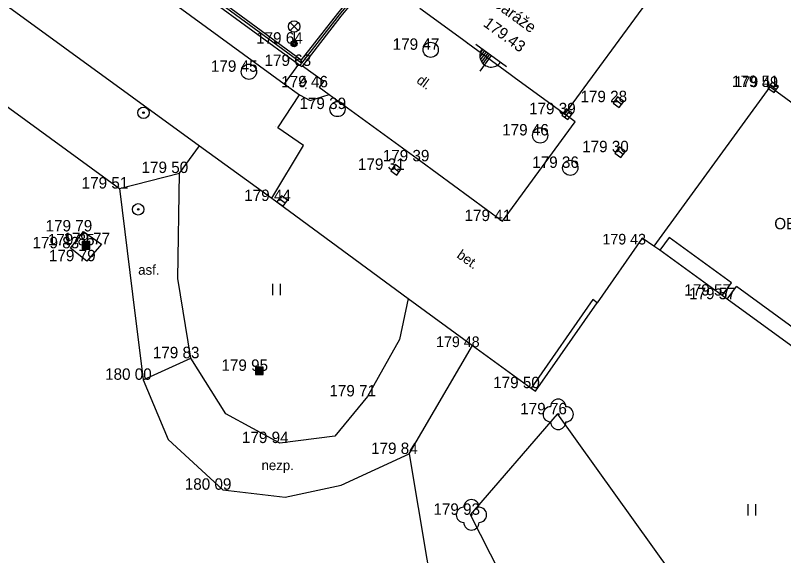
# Model space of a CAD drawing. Extents: x -537755 to -537431, y -1180722 to -1180510.
# Drawn here: x -537528.9 to -537478.3, y -1180686.8 to -1180651.3 of the extents above; entities that cross this region are included whole.
import ezdxf

# ---------------------------------------------------------------- set-up
doc = ezdxf.new("R2010")
doc.units = 0
for name, color, linetype in [('Vrstva 1', 7, 'Continuous'), ('Vrstva 10', 7, 'Continuous'), ('Vrstva 11', 7, 'Continuous'), ('Vrstva 21', 7, 'Continuous'), ('Vrstva 22', 7, 'Continuous'), ('Vrstva 23', 7, 'Continuous'), ('Vrstva 25', 7, 'Continuous'), ('Vrstva 27', 7, 'Continuous'), ('Vrstva 3', 7, 'Continuous'), ('Vrstva 33', 7, 'Continuous'), ('Vrstva 36', 7, 'Continuous'), ('Vrstva 37', 7, 'Continuous'), ('Vrstva 4', 7, 'Continuous'), ('Vrstva 40', 7, 'Continuous'), ('Vrstva 41', 7, 'Continuous'), ('Vrstva 5', 7, 'Continuous'), ('Vrstva 6', 7, 'Continuous'), ('Vrstva 7', 7, 'Continuous')]:
    doc.layers.add(name, color=color, linetype=linetype)

msp = doc.modelspace()

# ---------------------------------------------------------------- linework, layer by layer
at = {"layer": 'Vrstva 1'}
for p, q in [((-537507.45, -1180651.33), (-537507.45, -1180651.33)), ((-537510.53, -1180653.13), (-537510.53, -1180653.13)), ((-537510.5, -1180653.11), (-537510.5, -1180653.11)), ((-537499.14, -1180653.14), (-537499.14, -1180653.14)), ((-537501.548, -1180653.535), (-537501.548, -1180653.535)), ((-537513.5, -1180654.98), (-537513.5, -1180654.98)), ((-537510.02, -1180654.63), (-537510.02, -1180654.63)), ((-537509.99, -1180654.62), (-537509.99, -1180654.62)), ((-537509.973, -1180654.595), (-537509.973, -1180654.595)), ((-537508.78, -1180655.46), (-537508.78, -1180655.46)), ((-537496, -1180655.44), (-537496, -1180655.44)), ((-537511.18, -1180655.77), (-537511.18, -1180655.77)), ((-537508.873, -1180656.001), (-537508.873, -1180656.001)), ((-537508.577, -1180655.601), (-537508.577, -1180655.601)), ((-537479.24, -1180655.98), (-537479.24, -1180655.98)), ((-537479.24, -1180655.99), (-537479.24, -1180655.99)), ((-537510.18, -1180656.5), (-537510.18, -1180656.5)), ((-537509.7, -1180656.54), (-537509.7, -1180656.54)), ((-537489.2, -1180656.98), (-537489.2, -1180656.98)), ((-537507.678, -1180657.432), (-537507.678, -1180657.432)), ((-537507.61, -1180657.4), (-537507.61, -1180657.4)), ((-537492.72, -1180657.76), (-537492.72, -1180657.76)), ((-537492.69, -1180657.74), (-537492.69, -1180657.74)), ((-537492.58, -1180657.77), (-537492.58, -1180657.77)), ((-537492.053, -1180658.278), (-537492.053, -1180658.278)), ((-537511.76, -1180658.6), (-537511.76, -1180658.6)), ((-537494.348, -1180659.167), (-537494.348, -1180659.167)), ((-537494.32, -1180659.15), (-537494.32, -1180659.15)), ((-537516.93, -1180659.72), (-537516.93, -1180659.72)), ((-537509.92, -1180659.83), (-537509.92, -1180659.83)), ((-537489.09, -1180660.27), (-537489.09, -1180660.27)), ((-537489.08, -1180660.25), (-537489.08, -1180660.25)), ((-537502.201, -1180660.87), (-537502.201, -1180660.87)), ((-537503.83, -1180661.43), (-537503.83, -1180661.43)), ((-537503.77, -1180661.45), (-537503.77, -1180661.45)), ((-537492.37, -1180661.3), (-537492.37, -1180661.3)), ((-537492.33, -1180661.28), (-537492.33, -1180661.28)), ((-537518.17, -1180661.68), (-537518.17, -1180661.68)), ((-537518.06, -1180661.64), (-537518.06, -1180661.64)), ((-537522.01, -1180662.53), (-537522.01, -1180662.53)), ((-537522, -1180662.66), (-537522, -1180662.66)), ((-537511.99, -1180663.3), (-537511.99, -1180663.3)), ((-537511.31, -1180663.48), (-537511.31, -1180663.48)), ((-537511.28, -1180663.47), (-537511.28, -1180663.47)), ((-537520.78, -1180664.03), (-537520.78, -1180664.03)), ((-537496.821, -1180664.799), (-537496.821, -1180664.799)), ((-537524.37, -1180665.48), (-537524.37, -1180665.48)), ((-537487.61, -1180665.88), (-537487.61, -1180665.88)), ((-537525.23, -1180666.59), (-537525.23, -1180666.59)), ((-537524.24, -1180666.41), (-537524.24, -1180666.41)), ((-537524.22, -1180666.39), (-537524.22, -1180666.39)), ((-537524.22, -1180666.45), (-537524.22, -1180666.45)), ((-537523.2, -1180666.32), (-537523.2, -1180666.32)), ((-537487.92, -1180666.34), (-537487.92, -1180666.34)), ((-537486.87, -1180666.46), (-537486.87, -1180666.46)), ((-537486.86, -1180666.44), (-537486.86, -1180666.44)), ((-537486.47, -1180666.72), (-537486.47, -1180666.72)), ((-537524.15, -1180667.44), (-537524.15, -1180667.44)), ((-537518.17, -1180668.57), (-537518.17, -1180668.57)), ((-537518.14, -1180669.12), (-537518.14, -1180669.12)), ((-537521.16, -1180669.38), (-537521.16, -1180669.38)), ((-537521.16, -1180669.61), (-537521.16, -1180669.61)), ((-537482.37, -1180669.7), (-537482.37, -1180669.7)), ((-537482.06, -1180669.94), (-537482.06, -1180669.94)), ((-537503.6, -1180672.59), (-537503.6, -1180672.59)), ((-537498.86, -1180673.09), (-537498.86, -1180673.09)), ((-537517.32, -1180673.82), (-537517.32, -1180673.82)), ((-537517.14, -1180673.93), (-537517.14, -1180673.93)), ((-537512.82, -1180674.64), (-537512.82, -1180674.64)), ((-537512.81, -1180674.65), (-537512.81, -1180674.65)), ((-537512.8, -1180674.65), (-537512.8, -1180674.65)), ((-537520.46, -1180675.24), (-537520.46, -1180675.24)), ((-537494.94, -1180675.79), (-537494.94, -1180675.79)), ((-537494.86, -1180675.8), (-537494.86, -1180675.8)), ((-537505.71, -1180676.33), (-537505.71, -1180676.33)), ((-537515.02, -1180677.48), (-537515.02, -1180677.48)), ((-537493.16, -1180677.51), (-537493.16, -1180677.51)), ((-537518.8, -1180679.16), (-537518.8, -1180679.16)), ((-537507.85, -1180678.94), (-537507.85, -1180678.94)), ((-537511.46, -1180679.4), (-537511.46, -1180679.4)), ((-537502.97, -1180680.12), (-537502.97, -1180680.12)), ((-537507.43, -1180682.16), (-537507.43, -1180682.16)), ((-537515.22, -1180682.47), (-537515.22, -1180682.47)), ((-537511.12, -1180682.96), (-537511.12, -1180682.96)), ((-537498.87, -1180684.12), (-537498.87, -1180684.12))]:
    msp.add_line(p, q, dxfattribs=at)
at = {"layer": 'Vrstva 10'}
for p, q in [((-537528.74, -1180642.94), (-537511.18, -1180655.77)), ((-537532.96, -1180648.03), (-537516.759, -1180659.859)), ((-537516.759, -1180659.859), (-537511.99, -1180663.3)), ((-537511.99, -1180663.3), (-537503.026, -1180669.886)), ((-537487.633, -1180665.928), (-537490.591, -1180670.168)), ((-537486.87, -1180666.46), (-537487.633, -1180665.928)), ((-537503.026, -1180669.886), (-537498.794, -1180672.976)), ((-537490.878, -1180669.967), (-537494.94, -1180675.79)), ((-537490.591, -1180670.168), (-537490.878, -1180669.967)), ((-537498.794, -1180672.976), (-537494.94, -1180675.79))]:
    msp.add_line(p, q, dxfattribs=at)
for points in [[(-537511.18, -1180655.77), (-537510.18, -1180656.5), (-537509.477, -1180656.875), (-537508.221, -1180656.477)], [(-537502.97, -1180680.12), (-537501.22, -1180690.564)]]:
    msp.add_lwpolyline(points, dxfattribs=at)
at = {"layer": 'Vrstva 11'}
for p, q in [((-537543.39, -1180647.11), (-537522, -1180662.66)), ((-537510.233, -1180654.475), (-537511.18, -1180655.77)), ((-537508.873, -1180656.001), (-537508.221, -1180656.477)), ((-537508.221, -1180656.477), (-537502.201, -1180660.87)), ((-537492.053, -1180658.278), (-537492.72, -1180657.76)), ((-537496.821, -1180664.799), (-537492.053, -1180658.278)), ((-537502.201, -1180660.87), (-537496.821, -1180664.799)), ((-537518.17, -1180668.57), (-537518.06, -1180661.64)), ((-537522, -1180662.66), (-537521.16, -1180669.61)), ((-537517.32, -1180673.82), (-537518.17, -1180668.57)), ((-537521.16, -1180669.61), (-537520.46, -1180675.24)), ((-537494.656, -1180675.995), (-537490.591, -1180670.168)), ((-537502.97, -1180680.12), (-537498.794, -1180672.976)), ((-537520.46, -1180675.24), (-537517.32, -1180673.82)), ((-537494.94, -1180675.79), (-537494.656, -1180675.995)), ((-537507.43, -1180682.16), (-537502.97, -1180680.12))]:
    msp.add_line(p, q, dxfattribs=at)
for points in [[(-537509.973, -1180654.595), (-537508.577, -1180655.601), (-537508.873, -1180656.001)], [(-537511.99, -1180663.3), (-537509.92, -1180659.83), (-537511.608, -1180658.66), (-537510.18, -1180656.5)], [(-537522, -1180662.66), (-537518.06, -1180661.64), (-537516.759, -1180659.859)], [(-537503.026, -1180669.886), (-537503.6, -1180672.59), (-537505.71, -1180676.33)], [(-537511.46, -1180679.4), (-537515.02, -1180677.48), (-537517.32, -1180673.82)], [(-537520.46, -1180675.24), (-537518.8, -1180679.16), (-537515.22, -1180682.47)], [(-537505.71, -1180676.33), (-537507.85, -1180678.94), (-537511.46, -1180679.4)], [(-537515.22, -1180682.47), (-537511.12, -1180682.96), (-537507.43, -1180682.16)]]:
    msp.add_lwpolyline(points, dxfattribs=at)
at = {"layer": 'Vrstva 21'}
for centre, radius in [((-537520.433, -1180657.676), 0.375), ((-537520.433, -1180657.676), 0.05), ((-537520.78, -1180664.03), 0.375), ((-537520.78, -1180664.03), 0.05)]:
    msp.add_circle(centre, radius, dxfattribs=at)
at = {"layer": 'Vrstva 22'}
for centre in [(-537493.16, -1180677.51), (-537498.87, -1180684.12)]:
    msp.add_circle(centre, 0.05, dxfattribs=at)
for centre, start, end in [((-537493.16, -1180677.01), 0, 180), ((-537493.66, -1180677.51), 90, 270), ((-537492.66, -1180677.51), 270, 90), ((-537493.16, -1180678.01), 180, 0), ((-537498.87, -1180683.62), 0, 180), ((-537499.37, -1180684.12), 90, 270), ((-537498.37, -1180684.12), 270, 90), ((-537498.87, -1180684.62), 180, 0)]:
    msp.add_arc(centre, 0.5, start, end, dxfattribs=at)
at = {"layer": 'Vrstva 23'}
for p, q in [((-537498.92, -1180684.12), (-537493.21, -1180677.51)), ((-537493.21, -1180677.51), (-537479.81, -1180696.16)), ((-537491.98, -1180697.73), (-537498.92, -1180684.12))]:
    msp.add_line(p, q, dxfattribs=at)
at = {"layer": 'Vrstva 25'}
for points in [[(-537524.47, -1180666.64), (-537523.97, -1180666.64), (-537523.97, -1180666.14), (-537524.47, -1180666.14)], [(-537524.42, -1180666.59), (-537524.02, -1180666.59), (-537524.02, -1180666.19), (-537524.42, -1180666.19)], [(-537524.37, -1180666.54), (-537524.07, -1180666.54), (-537524.07, -1180666.24), (-537524.37, -1180666.24)], [(-537524.32, -1180666.49), (-537524.12, -1180666.49), (-537524.12, -1180666.29), (-537524.32, -1180666.29)], [(-537524.27, -1180666.44), (-537524.17, -1180666.44), (-537524.17, -1180666.34), (-537524.27, -1180666.34)], [(-537513.06, -1180674.9), (-537512.56, -1180674.9), (-537512.56, -1180674.4), (-537513.06, -1180674.4)], [(-537513.01, -1180674.85), (-537512.61, -1180674.85), (-537512.61, -1180674.45), (-537513.01, -1180674.45)], [(-537512.96, -1180674.8), (-537512.66, -1180674.8), (-537512.66, -1180674.5), (-537512.96, -1180674.5)], [(-537512.91, -1180674.75), (-537512.71, -1180674.75), (-537512.71, -1180674.55), (-537512.91, -1180674.55)], [(-537512.86, -1180674.7), (-537512.76, -1180674.7), (-537512.76, -1180674.6), (-537512.86, -1180674.6)]]:
    msp.add_lwpolyline(points, close=True, dxfattribs=at)
at = {"layer": 'Vrstva 27'}
for p, q in [((-537478.825, -1180656.151), (-537479.229, -1180655.857)), ((-537488.998, -1180657.127), (-537489.402, -1180656.833)), ((-537492.433, -1180657.568), (-537492.727, -1180657.972)), ((-537488.888, -1180660.417), (-537489.292, -1180660.123)), ((-537503.628, -1180661.577), (-537504.032, -1180661.283)), ((-537511.108, -1180663.627), (-537511.512, -1180663.333))]:
    msp.add_line(p, q, dxfattribs=at)
for points in [[(-537478.678, -1180655.949), (-537479.082, -1180655.655), (-537479.376, -1180656.059), (-537478.972, -1180656.353)], [(-537488.851, -1180656.925), (-537489.255, -1180656.631), (-537489.549, -1180657.035), (-537489.145, -1180657.329)], [(-537492.635, -1180657.421), (-537492.929, -1180657.825), (-537492.525, -1180658.119), (-537492.231, -1180657.715)], [(-537488.741, -1180660.215), (-537489.145, -1180659.921), (-537489.439, -1180660.325), (-537489.035, -1180660.619)], [(-537503.481, -1180661.375), (-537503.885, -1180661.081), (-537504.179, -1180661.485), (-537503.775, -1180661.779)], [(-537510.961, -1180663.425), (-537511.365, -1180663.131), (-537511.659, -1180663.535), (-537511.255, -1180663.829)]]:
    msp.add_lwpolyline(points, close=True, dxfattribs=at)
for centre in [(-537501.548, -1180653.535), (-537513.5, -1180654.98), (-537507.678, -1180657.432), (-537494.348, -1180659.167), (-537492.37, -1180661.3)]:
    msp.add_circle(centre, 0.5, dxfattribs=at)
at = {"layer": 'Vrstva 33'}
for p, q in [((-537510.795, -1180652.27), (-537510.265, -1180651.74)), ((-537510.795, -1180651.74), (-537510.265, -1180652.27)), ((-537510.53, -1180652.38), (-537510.53, -1180653.13))]:
    msp.add_line(p, q, dxfattribs=at)
for centre, radius in [((-537510.53, -1180652.005), 0.375), ((-537510.53, -1180653.13), 0.2), ((-537510.53, -1180653.13), 0.145), ((-537510.53, -1180653.13), 0.0876)]:
    msp.add_circle(centre, radius, dxfattribs=at)
at = {"layer": 'Vrstva 36'}
for p, q in [((-537511.934, -1180669.672), (-537511.934, -1180668.922)), ((-537511.434, -1180669.672), (-537511.434, -1180668.922)), ((-537480.665, -1180684.167), (-537480.665, -1180683.417)), ((-537480.165, -1180684.167), (-537480.165, -1180683.417))]:
    msp.add_line(p, q, dxfattribs=at)
at = {"layer": 'Vrstva 37'}
for p, q in [((-537496.554, -1180654.651), (-537498.574, -1180653.177)), ((-537498.129, -1180653.501), (-537498.293, -1180653.726)), ((-537498.016, -1180653.584), (-537498.315, -1180653.993)), ((-537497.564, -1180653.914), (-537498.306, -1180654.93)), ((-537497.903, -1180653.666), (-537498.275, -1180654.175)), ((-537497.79, -1180653.749), (-537498.205, -1180654.317)), ((-537497.677, -1180653.831), (-537498.116, -1180654.433))]:
    msp.add_line(p, q, dxfattribs=at)
msp.add_arc((-537497.569, -1180653.921), 0.75, 143.2425, 324.4886, dxfattribs=at)
at = {"layer": 'Vrstva 5'}
for p, q in [((-537492.72, -1180657.76), (-537486.85, -1180649.76)), ((-537499.464, -1180652.837), (-537499.109, -1180653.096)), ((-537496.314, -1180655.136), (-537495.965, -1180655.391)), ((-537479.24, -1180655.98), (-537486.87, -1180666.46)), ((-537471.17, -1180661.871), (-537479.24, -1180655.98)), ((-537493.17, -1180657.431), (-537492.72, -1180657.76)), ((-537485.863, -1180665.875), (-537486.47, -1180666.72)), ((-537481.758, -1180668.859), (-537485.863, -1180665.875)), ((-537486.47, -1180666.72), (-537486.87, -1180666.46)), ((-537482.37, -1180669.7), (-537486.47, -1180666.72)), ((-537482.37, -1180669.7), (-537481.758, -1180668.859)), ((-537482.06, -1180669.94), (-537481.448, -1180669.099)), ((-537472.568, -1180675.569), (-537481.448, -1180669.099)), ((-537482.06, -1180669.94), (-537482.37, -1180669.7)), ((-537473.18, -1180676.41), (-537482.06, -1180669.94))]:
    msp.add_line(p, q, dxfattribs=at)
at = {"layer": 'Vrstva 6'}
for p, q in [((-537502.258, -1180650.797), (-537499.464, -1180652.837)), ((-537499.109, -1180653.096), (-537496.314, -1180655.136)), ((-537495.965, -1180655.391), (-537493.17, -1180657.431))]:
    msp.add_line(p, q, dxfattribs=at)
at = {"layer": 'Vrstva 7'}
for p, q in [((-537524.09, -1180643.89), (-537510.065, -1180654.2)), ((-537524.304, -1180644.183), (-537510.233, -1180654.475)), ((-537510.043, -1180654.415), (-537524.197, -1180644.036)), ((-537510.233, -1180654.475), (-537510.02, -1180654.63))]:
    msp.add_line(p, q, dxfattribs=at)
for points in [[(-537505.502, -1180648.481), (-537507.684, -1180651.143), (-537510.065, -1180654.2)], [(-537505.381, -1180648.57), (-537507.567, -1180651.236), (-537510.043, -1180654.415)], [(-537505.26, -1180648.66), (-537507.45, -1180651.33), (-537509.973, -1180654.595), (-537510.02, -1180654.63)], [(-537524.37, -1180665.48), (-537523.2, -1180666.32), (-537524.15, -1180667.44), (-537525.23, -1180666.59), (-537524.37, -1180665.48)]]:
    msp.add_lwpolyline(points, dxfattribs=at)

# ---------------------------------------------------------------- texts
at = {"layer": 'Vrstva 3'}
for s, height, p in [('179 64 ', 0.75, (-537513.03, -1180653.13)), ('179 47 ', 0.75, (-537504.048, -1180653.535)), ('179 63 ', 0.75, (-537512.473, -1180654.595)), ('179 51 ', 0.75, (-537481.74, -1180655.98)), ('179 49 ', 0.7, (-537481.573, -1180655.99)), ('179 28 ', 0.75, (-537491.7, -1180656.98)), ('179 39 ', 0.75, (-537510.178, -1180657.432)), ('179 39 ', 0.75, (-537495.08, -1180657.77)), ('179 46 ', 0.75, (-537496.848, -1180659.167)), ('179 30 ', 0.75, (-537491.59, -1180660.27)), ('179 39 ', 0.75, (-537504.701, -1180660.87)), ('179 36 ', 0.75, (-537494.87, -1180661.3)), ('179 50 ', 0.75, (-537520.56, -1180661.64)), ('179 31 ', 0.75, (-537506.33, -1180661.43)), ('179 51 ', 0.75, (-537524.5, -1180662.66)), ('179 44 ', 0.75, (-537513.81, -1180663.48)), ('179 41 ', 0.75, (-537499.321, -1180664.799)), ('179 79 ', 0.75, (-537526.87, -1180665.48)), ('179 85 ', 0.75, (-537526.719, -1180666.39)), ('179 77 ', 0.75, (-537525.7, -1180666.32)), ('179 43 ', 0.7, (-537490.253, -1180666.34)), ('179 83 ', 0.75, (-537527.73, -1180666.59)), ('179 79 ', 0.75, (-537526.65, -1180667.44)), ('179 57 ', 0.75, (-537484.87, -1180669.7)), ('179 57 ', 0.75, (-537484.56, -1180669.94)), ('179 48 ', 0.7, (-537501.193, -1180673.09)), ('179 83 ', 0.75, (-537519.82, -1180673.82)), ('179 95 ', 0.75, (-537515.309, -1180674.65)), ('180 00 ', 0.75, (-537522.96, -1180675.24)), ('179 50 ', 0.75, (-537497.44, -1180675.79)), ('179 71 ', 0.75, (-537508.21, -1180676.33)), ('179 76 ', 0.75, (-537495.66, -1180677.51)), ('179 94 ', 0.75, (-537513.96, -1180679.4)), ('179 84 ', 0.75, (-537505.47, -1180680.12)), ('180 09 ', 0.75, (-537517.72, -1180682.47)), ('179 93 ', 0.75, (-537501.37, -1180684.12))]:
    msp.add_text(s, height=height, dxfattribs=at).set_placement(p)
at = {"layer": 'Vrstva 37'}
msp.add_text('179.43', height=0.75, rotation=323.8655, dxfattribs=at).set_placement((-537498.145, -1180651.932))
at = {"layer": 'Vrstva 4'}
for s, p in [('179 45 ', (-537516, -1180654.98)), ('179 46 ', (-537511.373, -1180656.001))]:
    msp.add_text(s, height=0.75, dxfattribs=at).set_placement(p)
at = {"layer": 'Vrstva 40'}
for s, rotation, p in [('b.', 323.848, (-537510.274, -1180655.752)), ('dl.', 323.848, (-537502.53, -1180655.661)), ('bet.', 324.5543, (-537499.883, -1180667.16))]:
    msp.add_text(s, height=0.65, rotation=rotation, dxfattribs=at).set_placement(p)
for s, p in [('asf.', (-537520.782, -1180668.331)), ('nezp.', (-537512.672, -1180681.182))]:
    msp.add_text(s, height=0.65, dxfattribs=at).set_placement(p)
at = {"layer": 'Vrstva 41'}
msp.add_text('Garáže', height=0.75, rotation=323.9048, dxfattribs=at).set_placement((-537497.615, -1180650.529))
msp.add_text('OBS JME', height=0.75, dxfattribs=at).set_placement((-537478.953, -1180665.341))

doc.saveas('drawing.dxf')
